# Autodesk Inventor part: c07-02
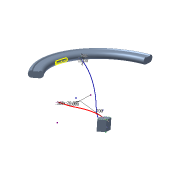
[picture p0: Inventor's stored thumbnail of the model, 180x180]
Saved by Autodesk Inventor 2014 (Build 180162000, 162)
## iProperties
Created: 2010-12
Part Number: c07-02
Document SubType Name: Modeling
Designer: Thom Tremblay
Density: 1 g/cm^3
Material: Generic
Appearance: Light Steel Blue
Author: Thom Tremblay
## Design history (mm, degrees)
sketch "Sketch2"
  geometry: L1 (0, 0)-(-11.43, 0); L2 (-11.43, 0)-(-11.43, 16.51); L3 (-11.43, 16.51)-(0, 16.51); L4 (0, 16.51)-(0, 0); L5 (-96.52, 66.04)-(-86.36, 66.04); L6 (-86.36, 76.2)-(-96.52, 76.2); L7 (-95.25, 74.93)-(-87.63, 74.93); L8 (-96.52, 76.2)-(-95.25, 74.93); L9 (-86.36, 76.2)-(-87.63, 74.93); A1 r 5.08 centre (-86.36, 71.12) between (-86.36, 66.04) and (-86.36, 76.2); A2 r 5.08 centre (-96.52, 71.12) between (-96.52, 76.2) and (-96.52, 66.04)
  constraints: 18 end point, 4 parallel, 4 point on circle, 4 tangent, 2 centre point, 2 horizontal, 2 perpendicular
  dimensions: "d6" = 16.51 distance of L1.end L2.end; "d7" = 22.86 diameter of L2 L4; "d10" = 5.08 radius of A1; "d11" = 20.32 dimension on A2 A1; "d12" = 3.81 distance from line of A1.centre L7; "d13" = 7.62 distance of L7.start L7.end; "d14" = 76.2 distance from line of L6.end L1; "d15" = 203.2 dimension on A2 L4
revolve "Revolution1" sketch "Sketch2" stored, may be unused: angle "d16" = 120 deg
sketch "Plane Sketch 1"
  geometry: L1 (-48.26, -83.589)-(-43.18, -74.79) reference; L2 (-48.26, 83.589)-(-43.18, 74.79) reference; L3 (0, 0)-(-85.598, 31.155); L4 (0, 0)-(-86.36, 0); A1 r 86.36 centre (0, 0) between (-43.18, 74.79) and (-43.18, -74.79) reference; A2 r 96.52 centre (0, 0) between (-48.26, 83.589) and (-48.26, -83.589) reference; 1 further point
  constraints: 4 end point, 1 point on circle
  dimensions: "d65" = 20 deg angle of L3 L4; "d66" = 91.09202 distance of L3.start L3.end
workplane "Work Plane2"
sketch "Sketch10"
  geometry: L1 (-8.89, 5.08)-(8.89, 5.08); L2 (-8.89, 2.54)-(8.89, 2.54); L3 (8.89, 7.62)-(-8.89, 7.62); A1 r 2.54 centre (-8.89, 5.08) between (-8.89, 7.62) and (-8.89, 2.54); A2 r 2.54 centre (8.89, 5.08) between (8.89, 2.54) and (8.89, 7.62); 2 further points
  constraints: 8 end point, 4 point on circle, 4 tangent, 2 centre point, 1 midpoint, 1 parallel, 1 vertical alignment
  dimensions: "d67" = 71.12 distance from line of L1 point (0, -66.04); "d68" = 17.78 distance of L3.start L3.end; "d69" = 2.54 radius of A2
sketch "Loft Sketch 1"
  node "Project from Sketch10"
sketch "Loft Sketch 2"
  geometry: C1 r 3.81 at (0, 7.62); 1 further point
  constraints: 1 centre point, 1 vertical alignment
  dimensions: "d63" = 7.62 diameter of C1; "d64" = 7.62 distance of point (0, 0) C1.centre
sketch "3D Sketch3"
  node "Project from Loft Sketch 2"
sketch "Rail Sketch 1"
  geometry: L1 (11.43, 0)-(-6.921, 0); L2 (76.378, 27.799)-(69.218, 25.193); L3 (0, 0)-(5.715, -9.899) reference; L4 (5.715, 9.899)-(0, 0) reference; A1 r 50.8 centre (86.592, -22.543) between (69.218, 25.193) and (53.126, 15.675); A2 r 63.293 centre (11.43, 63.293) between (11.43, 0) and (53.126, 15.675); A3 r 11.43 centre (0, 0) between (5.715, -9.899) and (5.715, 9.899) reference
  constraints: 4 end point, 4 point on circle, 3 tangent, 2 centre point, 1 horizontal
  dimensions: "d73" = 50.8 radius of A1; "d75" = 7.62 distance of L2.start L2.end; "d76" = 20 deg angle of L2 L1 (= d65)
sketch "Rail Sketch 2"
  geometry: L1 (-76.378, 71.12)-(-95.236, 71.12); L2 (-76.378, 71.12)-(-69.018, 69.148); L3 (-11.43, 7.62)-(5.882, 7.62); L4 (-11.43, 16.51)-(-11.43, 0) reference; A1 r 17.78 centre (-11.43, 25.4) between (-29.076, 23.224) and (-11.43, 7.62); A2 r 54.441 centre (-83.108, 16.562) between (-29.076, 23.224) and (-69.018, 69.148); 1 further point
  constraints: 6 end point, 4 point on circle, 3 tangent, 2 centre point, 1 horizontal, 1 perpendicular
  dimensions: "d78" = 15 deg angle of L2 L1; "d79" = 7.62 distance of L1.start L2.end; "d80" = 17.78 radius of A1
body "Solid1"
